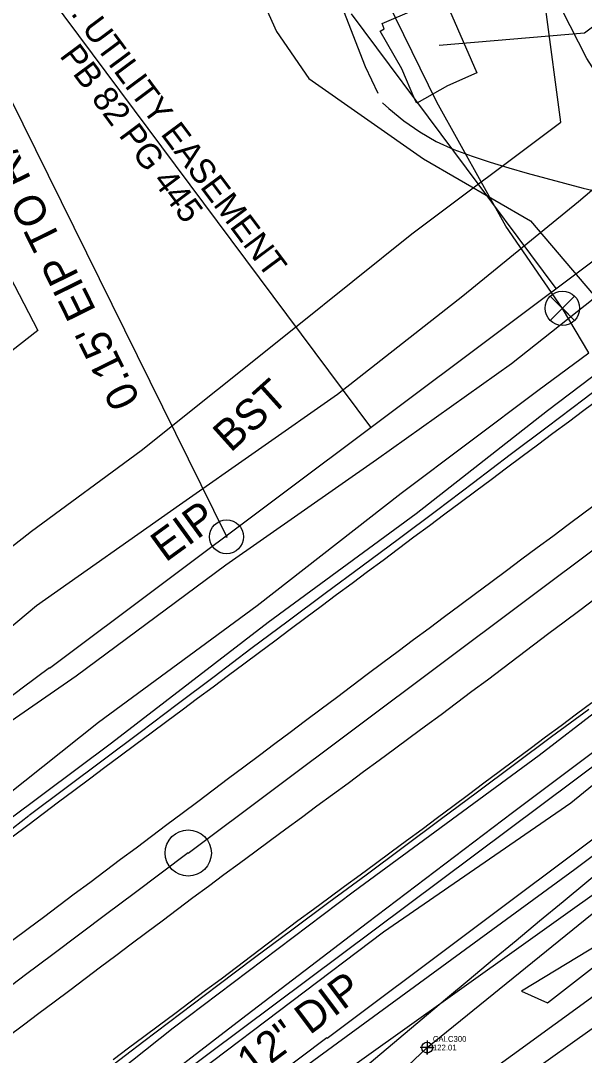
# Model space of a CAD drawing. Extents: x 2186615 to 2188822, y 629899 to 631820.
# Drawn here: x 2187114.7 to 2187187.8, y 630351.9 to 630486.1 of the extents above; entities that cross this region are included whole.
import ezdxf

# ---------------------------------------------------------------- set-up
doc = ezdxf.new("R2010")
doc.units = 0
for name, color, linetype in [('Exist Environmental Wetland Boundary', 7, 'Continuous'), ('Exist Environmental Wetland Boundary Cogo Elevation', 7, 'Continuous'), ('Exist Environmental Wetland Boundary Cogo Number', 7, 'Continuous'), ('Exist Environmental Wetland Boundary Cogo Point CELL', 7, 'Continuous'), ('Exist Guardrail', 7, 'Continuous'), ('Exist Horizontal Alignment', 7, 'Continuous'), ('Exist Horizontal Alignment Point', 7, 'Continuous'), ('Exist Hydro Jurisdictional Stream or Body of Water', 7, 'Continuous'), ('Exist Hydro Stream or Body of Water', 7, 'Continuous'), ('Exist Other Culture Area Outline', 7, 'Continuous'), ('Exist Other Culture Area Outline Leader', 7, 'Continuous'), ('Exist Property Iron Pin CELL', 7, 'Continuous'), ('Exist Property Iron Pin Text', 7, 'Continuous'), ('Exist Property Line', 7, 'Continuous'), ('Exist Property Line Text', 7, 'Continuous'), ('Exist Right of Way Easement Line', 7, 'Continuous'), ('Exist Right of Way Easement Line Text', 7, 'Continuous'), ('Exist Right of Way Line', 7, 'Continuous'), ('Exist Roads EOP', 7, 'Continuous'), ('Exist Roads EOP Other', 7, 'Continuous'), ('Exist Roads EOP Text', 7, 'Continuous'), ('Exist Roads EOT', 7, 'Continuous'), ('Exist Utilities Gas UG Line SUE LOS B', 7, 'Continuous'), ('Exist Utilities Sanitary Sewer UG Line', 7, 'Continuous'), ('Exist Utilities Sanitary Sewer UG Line Text', 7, 'Continuous'), ('Exist Utilities Telephone UG Cable SUE LOS C', 7, 'Continuous'), ('Exist Utilities Telephone UG FO SUE LOS B', 7, 'Continuous'), ('Exist Utilities TV UG Cable SUE LOS B', 7, 'Continuous'), ('Exist Utilities TV UG FO Cable SUE LOS B', 7, 'Continuous'), ('Exist Utilities Water UG Line SUE LOS B', 7, 'Continuous'), ('Exist Utilities Water Valve CELL', 7, 'Continuous'), ('Exist Vegetation Woods Line', 7, 'Continuous'), ('Scratch_Level_1', 7, 'Continuous')]:
    doc.layers.add(name, color=color, linetype=linetype)

msp = doc.modelspace()

# ---------------------------------------------------------------- linework, layer by layer
at = {"layer": 'Exist Environmental Wetland Boundary'}
msp.add_lwpolyline([(2187091.31, 630271.67), (2187085.68, 630287.81), (2187098.27, 630306.17), (2187117.25, 630318.39), (2187145.17, 630331.82), (2187167.38, 630352.86), (2187202.43, 630381.3), (2187228.67, 630401.09), (2187258.21, 630420.52), (2187282.17, 630435.85)], dxfattribs=at)
at = {"layer": 'Exist Environmental Wetland Boundary Cogo Point CELL'}
msp.add_lwpolyline([(2187167.38, 630353.76), (2187167.38, 630351.96), (2187167.38, 630352.86), (2187168.28, 630352.86), (2187166.48, 630352.86)], dxfattribs=at)
msp.add_circle((2187167.38, 630352.86), 0.703, dxfattribs=at)
at = {"layer": 'Exist Guardrail'}
msp.add_lwpolyline([(2187434.11, 630575.84), (2187413.64, 630560.33), (2187392.39, 630544.34), (2187371.19, 630528.33), (2187353.02, 630514.54), (2187332.38, 630498.86), (2187308.04, 630480.52), (2187282.88, 630461.57), (2187260.43, 630444.88), (2187240.79, 630430.16), (2187221.99, 630416.08), (2187199.87, 630399.4), (2187178.43, 630383.31), (2187159.65, 630369.05), (2187143.32, 630356.53), (2187128.81, 630345.41), (2187116.83, 630336.52)], dxfattribs=at)
at = {"layer": 'Exist Horizontal Alignment'}
msp.add_line((2187136.41, 630378.11), (2188520.86, 631416.04), dxfattribs=at)
msp.add_arc((2232330.7, 570095.74), 75342.48, 126.8592631, 127.0730198, dxfattribs=at)
at = {"layer": 'Exist Horizontal Alignment Point'}
msp.add_circle((2187136.41, 630378.11), 3, dxfattribs=at)
at = {"layer": 'Exist Hydro Jurisdictional Stream or Body of Water'}
msp.add_lwpolyline([(2187113.92, 630297.14), (2187128.08, 630305.06), (2187146.83, 630323.39), (2187171.96, 630343.37), (2187197.32, 630361.43)], dxfattribs=at)
at = {"layer": 'Exist Hydro Stream or Body of Water'}
msp.add_lwpolyline([(2187182.98, 630358.66), (2187194.89, 630367.91), (2187211.56, 630372.65), (2187206.21, 630373.5), (2187198.39, 630371.54), (2187179.6, 630360.19), (2187182.98, 630358.66)], dxfattribs=at)
at = {"layer": 'Exist Other Culture Area Outline'}
msp.add_lwpolyline([(2187169.53, 630489.18), (2187173.82, 630479.34), (2187170.02, 630477.66), (2187166.05, 630475.41), (2187165.8, 630475.86), (2187164.11, 630479.85), (2187161.27, 630484.75), (2187161.83, 630485.05), (2187161.55, 630485.74), (2187169.53, 630489.18)], dxfattribs=at)
at = {"layer": 'Exist Other Culture Area Outline Leader'}
msp.add_lwpolyline([(2187168.93, 630482.94), (2187187.8, 630484.54), (2187191.69, 630487.45)], dxfattribs=at)
at = {"layer": 'Exist Property Iron Pin CELL'}
for radius in [2.2, 0.0707]:
    msp.add_circle((2187141.37, 630419.14), radius, dxfattribs=at)
at = {"layer": 'Exist Property Line'}
msp.add_line((2187037.28, 630630.08), (2187141.31, 630419.27), dxfattribs=at)
at = {"layer": 'Exist Right of Way Easement Line'}
for p, q in [((2187160.08, 630433.35), (2187115.55, 630493.13)), ((2187157.53, 630486.99), (2187184.09, 630451.35))]:
    msp.add_line(p, q, dxfattribs=at)
at = {"layer": 'Exist Right of Way Line'}
for p, q in [((2187118.41, 630402.11), (2188502.83, 631440.02)), ((2187154.4, 630354.1), (2188538.85, 631392.04))]:
    msp.add_line(p, q, dxfattribs=at)
for centre, radius, start, end in [((2189028.8, 628141.74), 2893.55, 125.65722, 135.70821), ((2232330.7, 570095.74), 75372.48, 126.8592631, 127.0730198), ((2189028.8, 628141.74), 2763.55, 125.65722, 135.70821), ((2232330.7, 570095.74), 75312.48, 126.8592631, 127.0730198)]:
    msp.add_arc(centre, radius, start, end, dxfattribs=at)
at = {"layer": 'Exist Roads EOP'}
for points in [[(2187161.61, 630475.43), (2187162.42, 630474.69), (2187164.36, 630473.12), (2187166.42, 630471.7), (2187168.57, 630470.43), (2187170.85, 630469.41), (2187173.2, 630468.54), (2187175.57, 630467.76), (2187177.96, 630467.03), (2187180.36, 630466.33), (2187182.77, 630465.66), (2187185.18, 630465.01), (2187187.6, 630464.38), (2187190.03, 630463.79)], [(2187115.76, 630383), (2187120.56, 630386.6), (2187125.36, 630390.2), (2187130.16, 630393.81), (2187134.95, 630397.42), (2187139.75, 630401.02), (2187144.54, 630404.63), (2187149.35, 630408.22), (2187154.16, 630411.81), (2187158.97, 630415.39), (2187163.78, 630418.98), (2187168.59, 630422.56), (2187173.38, 630426.18), (2187178.16, 630429.8), (2187182.95, 630433.42), (2187187.73, 630437.05), (2187192.51, 630440.67)], [(2187188.33, 630396.75), (2187183.51, 630393.18), (2187178.7, 630389.59), (2187173.9, 630386), (2187169.09, 630382.4), (2187164.28, 630378.82), (2187159.46, 630375.25), (2187154.64, 630371.67), (2187149.82, 630368.1), (2187145.01, 630364.51), (2187140.22, 630360.9), (2187135.44, 630357.28), (2187130.65, 630353.65), (2187125.87, 630350.03)], [(2187103.82, 630373.84), (2187105.81, 630375.34), (2187107.81, 630376.85), (2187109.8, 630378.36), (2187111.78, 630379.88), (2187113.76, 630381.41), (2187115.75, 630382.99)]]:
    msp.add_lwpolyline(points, dxfattribs=at)
at = {"layer": 'Exist Roads EOP Other'}
for points in [[(2187138.6, 630534.63), (2187139.91, 630531.34), (2187144.17, 630522.21), (2187147.14, 630513.9), (2187151.29, 630502.42), (2187154.7, 630492.1), (2187159.33, 630480.16), (2187161, 630476.69)], [(2187099.63, 630474.5), (2187101.71, 630468.41), (2187106.89, 630462), (2187113.29, 630452.91), (2187116.9, 630445.92), (2187109.49, 630440.17), (2187094.63, 630428.56), (2187086.08, 630422.18)]]:
    msp.add_lwpolyline(points, dxfattribs=at)
at = {"layer": 'Exist Roads EOT'}
for points in [[(2187113.59, 630380.22), (2187115.59, 630381.72), (2187117.59, 630383.23), (2187119.58, 630384.73), (2187121.58, 630386.23), (2187123.58, 630387.73), (2187125.58, 630389.23), (2187127.59, 630390.72), (2187129.59, 630392.21), (2187131.6, 630393.71), (2187133.61, 630395.2), (2187135.61, 630396.69), (2187137.62, 630398.19), (2187139.62, 630399.68), (2187141.63, 630401.17), (2187143.63, 630402.66), (2187145.64, 630404.16), (2187147.64, 630405.65), (2187149.64, 630407.15), (2187151.65, 630408.65), (2187153.65, 630410.14), (2187155.65, 630411.64), (2187157.65, 630413.13), (2187159.66, 630414.63), (2187161.66, 630416.12), (2187163.66, 630417.62), (2187165.67, 630419.12), (2187167.67, 630420.61), (2187169.67, 630422.11), (2187171.68, 630423.6), (2187173.68, 630425.1), (2187175.68, 630426.59), (2187177.69, 630428.09), (2187179.69, 630429.58), (2187181.69, 630431.08), (2187183.7, 630432.57), (2187185.7, 630434.07), (2187187.71, 630435.56), (2187189.71, 630437.06)], [(2187113.63, 630366.8), (2187115.63, 630368.3), (2187117.63, 630369.8), (2187119.63, 630371.3), (2187121.63, 630372.8), (2187123.63, 630374.3), (2187125.63, 630375.8), (2187127.63, 630377.3), (2187129.63, 630378.8), (2187131.63, 630380.3), (2187133.63, 630381.8), (2187135.63, 630383.3), (2187137.63, 630384.8), (2187139.63, 630386.3), (2187141.63, 630387.8), (2187143.63, 630389.3), (2187145.63, 630390.8), (2187147.63, 630392.3), (2187149.62, 630393.8), (2187151.62, 630395.3), (2187153.62, 630396.8), (2187155.62, 630398.3), (2187157.62, 630399.81), (2187159.62, 630401.31), (2187161.62, 630402.81), (2187163.62, 630404.3), (2187165.63, 630405.8), (2187167.63, 630407.29), (2187169.64, 630408.79), (2187171.64, 630410.28), (2187173.65, 630411.77), (2187175.65, 630413.27), (2187177.66, 630414.76), (2187179.66, 630416.26), (2187181.67, 630417.75), (2187183.67, 630419.24), (2187185.68, 630420.74), (2187187.68, 630422.23), (2187189.68, 630423.72)], [(2187113.03, 630354.31), (2187115.03, 630355.81), (2187117.03, 630357.31), (2187119.03, 630358.81), (2187121.03, 630360.31), (2187123.03, 630361.82), (2187125.03, 630363.32), (2187127.02, 630364.82), (2187129.02, 630366.32), (2187131.02, 630367.82), (2187133.02, 630369.32), (2187135.02, 630370.82), (2187137.02, 630372.32), (2187139.03, 630373.82), (2187141.04, 630375.3), (2187143.05, 630376.79), (2187145.06, 630378.27), (2187147.07, 630379.76), (2187149.08, 630381.24), (2187151.09, 630382.73), (2187153.1, 630384.21), (2187155.12, 630385.7), (2187157.13, 630387.18), (2187159.14, 630388.67), (2187161.15, 630390.15), (2187163.16, 630391.64), (2187165.17, 630393.12), (2187167.18, 630394.61), (2187169.19, 630396.09), (2187171.19, 630397.59), (2187173.19, 630399.09), (2187175.19, 630400.6), (2187177.19, 630402.1), (2187179.18, 630403.61), (2187181.18, 630405.11), (2187183.18, 630406.62), (2187185.17, 630408.12), (2187187.17, 630409.62), (2187189.17, 630411.13)], [(2187188.76, 630397.61), (2187186.76, 630396.12), (2187184.75, 630394.62), (2187182.75, 630393.13), (2187180.75, 630391.64), (2187178.74, 630390.14), (2187176.74, 630388.64), (2187174.74, 630387.15), (2187172.73, 630385.65), (2187170.73, 630384.16), (2187168.72, 630382.66), (2187166.72, 630381.17), (2187164.71, 630379.68), (2187162.7, 630378.2), (2187160.69, 630376.71), (2187158.68, 630375.23), (2187156.66, 630373.75), (2187154.65, 630372.27), (2187152.63, 630370.79), (2187150.61, 630369.31), (2187148.62, 630367.8), (2187146.63, 630366.29), (2187144.65, 630364.77), (2187142.66, 630363.25), (2187140.66, 630361.75), (2187138.66, 630360.25), (2187136.66, 630358.75), (2187134.66, 630357.25), (2187132.66, 630355.76), (2187130.65, 630354.26), (2187128.65, 630352.77), (2187126.65, 630351.27)]]:
    msp.add_lwpolyline(points, dxfattribs=at)
at = {"layer": 'Exist Utilities Gas UG Line SUE LOS B'}
for points in [[(2187126.47, 630392.39), (2187146.75, 630408.06), (2187165.95, 630422.17), (2187183, 630435.52), (2187198.84, 630447.53), (2187220.79, 630463.61), (2187230.74, 630480.09), (2187238.84, 630491.28), (2187252.93, 630500.78), (2187264.62, 630507.02), (2187278.9, 630518.02), (2187291.16, 630525.79), (2187304.76, 630536.93), (2187314.39, 630544.2), (2187331.5, 630558.33), (2187350.48, 630574.64)], [(2186961.34, 630266.71), (2186999.6, 630296.45), (2187019.95, 630311.63), (2187033.4, 630322.07), (2187051.7, 630335.62), (2187070.69, 630349.82), (2187099.69, 630372.44), (2187126.47, 630392.39)]]:
    msp.add_lwpolyline(points, dxfattribs=at)
at = {"layer": 'Exist Utilities Sanitary Sewer UG Line'}
msp.add_line((2186953.53, 630213.34), (2187280.26, 630457.75), dxfattribs=at)
at = {"layer": 'Exist Utilities Telephone UG Cable SUE LOS C'}
msp.add_lwpolyline([(2187048.71, 630267.56), (2187045.35, 630278.25), (2187057.02, 630287.25), (2187078.19, 630303.42), (2187102.04, 630322.51), (2187119.95, 630336.14), (2187137.94, 630349.88), (2187161.71, 630367.86), (2187186.02, 630384.64), (2187207.08, 630401.8), (2187231.6, 630419.79), (2187256.85, 630438.71), (2187278.85, 630453.8), (2187296.98, 630467.54), (2187304.94, 630472.73), (2187317.62, 630478.55), (2187327.51, 630484.53), (2187332.68, 630485.86), (2187337.99, 630482.8), (2187346.28, 630476.8)], dxfattribs=at)
at = {"layer": 'Exist Utilities Telephone UG FO SUE LOS B'}
for points in [[(2187129.46, 630527.76), (2187139.46, 630503.38), (2187147.83, 630484.7), (2187152.04, 630478.59), (2187166.91, 630468.2), (2187180.79, 630460.12), (2187192.4, 630446.46), (2187206, 630427.52), (2187215.4, 630412.66), (2187218.54, 630406.18), (2187228.54, 630393.28)], [(2187049.38, 630270.15), (2187042.5, 630278.37), (2187044.06, 630284.34), (2187057.31, 630294.02), (2187075.64, 630307.12), (2187098.73, 630326.67), (2187116.95, 630341.49), (2187134.44, 630355.42), (2187157.81, 630373.05), (2187181.9, 630390.79), (2187205.12, 630408.7), (2187231.97, 630429.32), (2187252.44, 630444.7), (2187272.54, 630459.69), (2187294.09, 630476.32), (2187309.64, 630487.97), (2187327.19, 630501.03), (2187332.67, 630500.22), (2187340.34, 630491.39), (2187346.28, 630476.8)], [(2187121.86, 630401.1), (2187141.28, 630415.49), (2187160.8, 630429.17), (2187178.34, 630441.63), (2187193.04, 630453.32)], [(2186916.21, 630248.6), (2186927.38, 630260.09), (2186942.37, 630270.68), (2186955.34, 630280.32), (2186974.86, 630297.18), (2186993.47, 630310.39), (2187007.03, 630317.72), (2187028, 630334.1), (2187044.5, 630346.39), (2187064.77, 630361.14), (2187093.15, 630381.24), (2187121.86, 630401.1)]]:
    msp.add_lwpolyline(points, dxfattribs=at)
at = {"layer": 'Exist Utilities TV UG Cable SUE LOS B'}
for points in [[(2187116.07, 630419.88), (2187130.29, 630430.32), (2187150.11, 630446.17), (2187165.4, 630458.46), (2187184.72, 630472.95), (2187182.78, 630487.57), (2187170.53, 630511.09), (2187150.61, 630543.66)], [(2187009.04, 630243.54), (2187005.06, 630241.81), (2186997.15, 630243.52), (2186988.34, 630246.09), (2186958.26, 630264.28), (2186948.02, 630270.76), (2186941.05, 630277.35), (2186953.05, 630286.67), (2186970.62, 630302.57), (2186987.79, 630317.23), (2186999.43, 630326.74), (2187020.89, 630345.03), (2187036.72, 630358.42), (2187055.34, 630373.05), (2187084.13, 630394.81), (2187116.07, 630419.88)]]:
    msp.add_lwpolyline(points, dxfattribs=at)
at = {"layer": 'Exist Utilities TV UG FO Cable SUE LOS B'}
for points in [[(2187116.73, 630410.24), (2187135.27, 630423.28), (2187155.78, 630437.63), (2187172.03, 630450.4), (2187187.01, 630462.63), (2187195.4, 630469.76), (2187188.11, 630481.18), (2187177.24, 630502.53), (2187165.51, 630524.63), (2187155.03, 630546.98)], [(2186956.68, 630278.76), (2186994.31, 630309.11), (2187006.19, 630319.06), (2187027.03, 630336.52), (2187042.65, 630349.62), (2187062.09, 630364.95), (2187089.07, 630387.06), (2187116.73, 630410.24)]]:
    msp.add_lwpolyline(points, dxfattribs=at)
at = {"layer": 'Exist Utilities Water UG Line SUE LOS B'}
for points in [[(2187181.75, 630438.12), (2187188.37, 630443.02), (2187184.93, 630448.76), (2187177.6, 630459.46), (2187168.65, 630475.53), (2187158.99, 630495.24), (2187152.4, 630508.06), (2187139.39, 630535.22)], [(2187124.77, 630395.09), (2187145.32, 630410.22), (2187164.02, 630424.81), (2187181.75, 630438.12)], [(2186959.77, 630269.32), (2186998.9, 630299.18), (2187017.82, 630313.83), (2187031.57, 630324.4), (2187049.45, 630337.67), (2187068.61, 630351.56), (2187098.38, 630374.13), (2187124.77, 630395.09)]]:
    msp.add_lwpolyline(points, dxfattribs=at)
at = {"layer": 'Exist Utilities Water Valve CELL'}
msp.add_lwpolyline([(2187186.5, 630450.36), (2187183.35, 630447.21), (2187184.93, 630448.79), (2187186.5, 630447.21), (2187183.35, 630450.36)], dxfattribs=at)
msp.add_circle((2187184.93, 630448.79), 2.23, dxfattribs=at)
at = {"layer": 'Exist Vegetation Woods Line'}
for points in [[(2187105.73, 630299.09), (2187150.8, 630331.83), (2187206.11, 630372.03), (2187256.07, 630407.26), (2187300.91, 630439.29), (2187349.47, 630473.88), (2187396.87, 630507.87), (2187440.69, 630538.21), (2187466.07, 630555.07), (2187474.72, 630557.75), (2187481.17, 630558.92), (2187486.05, 630559.68), (2187489.3, 630561.14), (2187491.38, 630563.95), (2187492.45, 630570.17), (2187494.25, 630572.31)], [(2187230.5, 630408.89), (2187277.27, 630443.25), (2187318.86, 630473.26), (2187330.63, 630477.31), (2187307.15, 630458.86), (2187234.21, 630405.64), (2187193, 630375.63), (2187170.08, 630359.23), (2187132.55, 630332.44), (2187105.52, 630312.12)], [(2187103.49, 630315.88), (2187138.52, 630340.83), (2187186.53, 630376), (2187214.46, 630397), (2187230.5, 630408.89)]]:
    msp.add_lwpolyline(points, dxfattribs=at)
at = {"layer": 'Scratch_Level_1'}
msp.add_arc((2189028.8, 628141.74), 2815.55, 125.65722, 135.70821, dxfattribs=at)

# ---------------------------------------------------------------- texts
at = {"layer": 'Exist Environmental Wetland Boundary Cogo Elevation'}
msp.add_text('122.01', height=0.75, dxfattribs=at).set_placement((2187168.13, 630352.49))
at = {"layer": 'Exist Environmental Wetland Boundary Cogo Number'}
msp.add_text('CALC300', height=0.75, dxfattribs=at).set_placement((2187168.13, 630353.61))
at = {"layer": 'Exist Property Iron Pin Text'}
msp.add_text('EIP', height=4, rotation=36.0491, dxfattribs=at).set_placement((2187133.46, 630415.76))
at = {"layer": 'Exist Property Line Text'}
msp.add_text("0.15' EIP TO R/W", height=4, rotation=116.266, dxfattribs=at).set_placement((2187130.24, 630436.91))
at = {"layer": 'Exist Right of Way Easement Line Text'}
for s, p in [('EX. UTILITY EASEMENT', (2187117.68, 630491.61)), ('PB 82 PG 445', (2187119.63, 630481.53))]:
    msp.add_text(s, height=3.2, rotation=306.6851, dxfattribs=at).set_placement(p)
at = {"layer": 'Exist Roads EOP Text'}
msp.add_text('BST', height=4, rotation=41.9577, dxfattribs=at).set_placement((2187141.89, 630429.99))
at = {"layer": 'Exist Utilities Sanitary Sewer UG Line Text'}
msp.add_text('12" DIP', height=4, rotation=36.7978, dxfattribs=at).set_placement((2187144.68, 630348.84))

doc.saveas('drawing.dxf')
